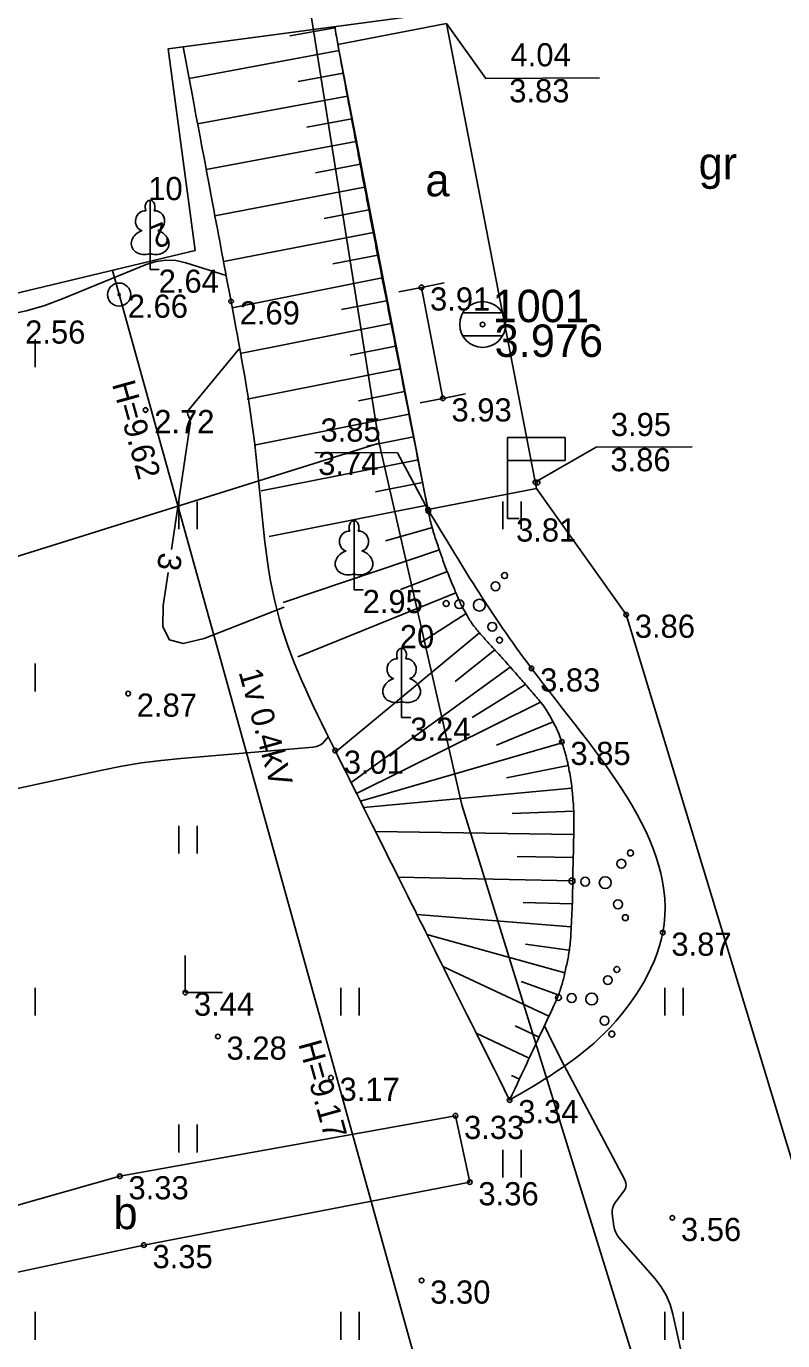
# Model space of a CAD drawing. Extents: x 321079 to 321220, y 257030 to 257220.
# Drawn here: x 321153.21 to 321169.55, y 257130.98 to 257159.36 of the extents above; entities that cross this region are included whole.
import ezdxf

# ---------------------------------------------------------------- set-up
doc = ezdxf.new("R2010")
doc.units = 0
for name, color, linetype in [('BUVE_SOLS_####_####_#', 7, 'Continuous'), ('CELI_CAPM_####_####_#', 7, 'Continuous'), ('CELI_CMAL_####_####_#', 7, 'Continuous'), ('CELI_CSEG_####_TKST_#', 7, 'Continuous'), ('CELI_ELEM_####_####_#', 7, 'Continuous'), ('ELEK_ELEM_####_####_#', 7, 'Continuous'), ('ELEK_VADV_ZSPR_####_#', 7, 'Continuous'), ('ELEK_VADV_ZSPR_TKST_#', 7, 'Continuous'), ('GEOD_ELEM_####_####_#', 7, 'Continuous'), ('GEOD_ELEM_####_TKST_#', 7, 'Continuous'), ('RAMI_UZMR_####_####_#', 7, 'Continuous'), ('RELJ_AATZ_####_TKST_#', 7, 'Continuous'), ('RELJ_ELEM_####_####_#', 7, 'Continuous'), ('RELJ_HORZ_####_TKST_#', 7, 'Continuous'), ('RELJ_HORZ_PAMT_####_#', 7, 'Continuous'), ('RELJ_HORZ_PUSH_####_#', 7, 'Continuous'), ('RELJ_NOGA_####_####_#', 7, 'Continuous'), ('RELJ_NOGL_####_####_#', 7, 'Continuous'), ('ROBZ_UZMR_####_####_#', 7, 'Continuous'), ('TERT_DIAM_####_TKST_#', 7, 'Continuous'), ('TERT_ELEM_####_####_#', 7, 'Continuous'), ('TERT_KONT_####_####_#', 7, 'Continuous')]:
    doc.layers.add(name, color=color, linetype=linetype)

msp = doc.modelspace()

# ---------------------------------------------------------------- linework, layer by layer
at = {"layer": 'BUVE_SOLS_####_####_#'}
for p, q in [((321162.233, 257153.819), (321161.742, 257153.724)), ((321161.251, 257153.629), (321161.742, 257153.724)), ((321162.206, 257151.328), (321161.742, 257153.724)), ((321161.715, 257151.233), (321162.206, 257151.328)), ((321162.697, 257151.423), (321162.206, 257151.328))]:
    msp.add_line(p, q, dxfattribs=at)
at = {"layer": 'CELI_CAPM_####_####_#'}
msp.add_lwpolyline([(321162.284, 257159.421), (321164.229, 257149.382), (321161.884, 257148.928), (321159.939, 257158.967)], close=True, dxfattribs=at)
at = {"layer": 'CELI_CMAL_####_####_#'}
for points in [[(321164.229, 257149.382), (321166.166, 257146.657), (321169.755, 257134.824), (321173.111, 257121.931), (321175.798, 257109.619)], [(321149.02, 257131.603), (321155.747, 257133.045), (321162.788, 257134.403), (321162.477, 257135.836), (321155.228, 257134.532), (321148.802, 257132.714)]]:
    msp.add_lwpolyline(points, dxfattribs=at)
at = {"layer": 'CELI_ELEM_####_####_#'}
for p, q in [((321163.601, 257148.735), (321163.601, 257150.485)), ((321163.601, 257150.485), (321164.851, 257150.485)), ((321164.851, 257150.485), (321164.851, 257149.985)), ((321163.601, 257149.985), (321164.851, 257149.985)), ((321163.601, 257148.735), (321163.851, 257148.735))]:
    msp.add_line(p, q, dxfattribs=at)
at = {"layer": 'ELEK_ELEM_####_####_#'}
for radius in [0.25, 0.0225]:
    msp.add_circle((321155.212, 257153.568), radius, dxfattribs=at)
at = {"layer": 'ELEK_VADV_ZSPR_####_#'}
msp.add_line((321165.672, 257115.939), (321155.067, 257154.09), dxfattribs=at)
at = {"layer": 'GEOD_ELEM_####_####_#'}
for p, q in [((321162.635, 257153.171), (321163.493, 257153.171)), ((321162.635, 257152.676), (321163.493, 257152.676))]:
    msp.add_line(p, q, dxfattribs=at)
for radius in [0.495, 0.05]:
    msp.add_circle((321163.064, 257152.923), radius, dxfattribs=at)
at = {"layer": 'RAMI_UZMR_####_####_#'}
msp.add_lwpolyline([(321107.5, 257141.5), (321108.611, 257133.395), (321131.584, 257099.382), (321150.327, 257105.322), (321177.121, 257109.842), (321183.308, 257111.386), (321177.517, 257137.442), (321172.561, 257161.05), (321156.27, 257158.872), (321156.852, 257154.517), (321139.352, 257150.329), (321114.57, 257145.337)], close=True, dxfattribs=at)
at = {"layer": 'RELJ_AATZ_####_TKST_#'}
for points in [[(321162.284, 257159.421), (321163.132, 257158.232), (321165.587, 257158.246)], [(321161.884, 257148.928), (321161.225, 257150.15), (321159.442, 257150.158)], [(321164.203, 257149.517), (321165.514, 257150.274), (321167.589, 257150.282)]]:
    msp.add_lwpolyline(points, dxfattribs=at)
at = {"layer": 'RELJ_ELEM_####_####_#'}
for centre in [(321161.742, 257153.724), (321157.629, 257153.423), (321162.206, 257151.328), (321155.782, 257151.076), (321155.785, 257151.077), (321164.203, 257149.517), (321164.251, 257149.509), (321161.884, 257148.928), (321161.893, 257148.894), (321166.166, 257146.657), (321164.12, 257145.497), (321155.407, 257144.954), (321164.775, 257143.911), (321159.879, 257143.721), (321166.956, 257139.792), (321156.642, 257138.496), (321157.346, 257137.548), (321159.787, 257136.658), (321163.648, 257136.176), (321162.477, 257135.836), (321155.228, 257134.532), (321162.788, 257134.403), (321167.163, 257133.632), (321155.747, 257133.045), (321161.746, 257132.28)]:
    msp.add_circle(centre, 0.05, dxfattribs=at)
at = {"layer": 'RELJ_HORZ_PAMT_####_#'}
for points in [[(321156.342, 257148.061), (321156.749, 257150.775), (321156.751, 257150.801), (321156.75, 257150.828), (321156.745, 257150.854), (321156.737, 257150.879), (321156.695, 257150.981), (321156.689, 257151.006), (321156.689, 257151.029), (321156.696, 257151.052), (321156.71, 257151.074), (321157.808, 257152.399)], [(321158.776, 257146.816), (321157.051, 257146.145), (321156.598, 257146.035), (321156.299, 257146.117), (321156.154, 257146.391), (321156.161, 257146.857), (321156.268, 257147.567)], [(321150.909, 257141.534), (321151.016, 257141.573), (321151.199, 257141.679), (321151.365, 257141.818), (321152.001, 257142.441), (321152.167, 257142.583), (321152.348, 257142.698), (321152.543, 257142.786), (321152.753, 257142.847), (321154.846, 257143.299), (321155.268, 257143.383), (321155.693, 257143.454), (321156.119, 257143.511), (321156.548, 257143.554), (321159.404, 257143.796), (321159.478, 257143.809), (321159.545, 257143.836), (321159.604, 257143.877), (321159.656, 257143.932), (321159.732, 257144.027)]]:
    msp.add_lwpolyline(points, dxfattribs=at)
at = {"layer": 'RELJ_HORZ_PUSH_####_#'}
for points in [[(321149.681, 257152.801), (321152.406, 257153.078), (321152.806, 257153.133), (321153.2, 257153.217), (321153.586, 257153.328), (321153.965, 257153.468), (321155.798, 257154.217), (321156.01, 257154.284), (321156.223, 257154.313), (321156.438, 257154.303), (321156.654, 257154.254), (321157.523, 257153.982), (321157.524, 257153.982)], [(321164.4, 257137.779), (321164.485, 257137.601), (321164.567, 257137.435), (321164.65, 257137.269), (321164.734, 257137.104), (321164.82, 257136.94), (321166.136, 257134.454), (321166.161, 257134.391), (321166.165, 257134.329), (321166.15, 257134.269), (321166.116, 257134.21), (321165.934, 257133.972), (321165.898, 257133.916), (321165.875, 257133.856), (321165.864, 257133.794), (321165.866, 257133.727), (321165.897, 257133.456), (321165.91, 257133.39), (321165.932, 257133.328), (321165.963, 257133.271), (321166.003, 257133.217), (321166.789, 257132.319), (321166.923, 257132.146), (321167.032, 257131.961), (321167.116, 257131.763), (321167.176, 257131.552), (321167.47, 257130.219)]]:
    msp.add_lwpolyline(points, dxfattribs=at)
at = {"layer": 'RELJ_NOGA_####_####_#'}
for p, q in [((321159.873, 257159.331), (321158.899, 257159.154)), ((321159.963, 257158.839), (321156.723, 257158.237)), ((321160.054, 257158.348), (321159.082, 257158.167)), ((321160.145, 257157.856), (321156.908, 257157.254)), ((321160.237, 257157.365), (321159.266, 257157.184)), ((321160.328, 257156.873), (321157.093, 257156.271)), ((321160.42, 257156.382), (321159.451, 257156.195)), ((321160.515, 257155.891), (321157.282, 257155.267)), ((321160.609, 257155.4), (321159.639, 257155.213)), ((321160.704, 257154.909), (321157.467, 257154.285)), ((321160.799, 257154.418), (321159.827, 257154.23)), ((321160.893, 257153.927), (321157.653, 257153.285)), ((321160.991, 257153.436), (321160.015, 257153.243)), ((321161.088, 257152.946), (321157.823, 257152.299)), ((321161.185, 257152.455), (321160.2, 257152.26)), ((321161.282, 257151.965), (321157.977, 257151.31)), ((321161.379, 257151.474), (321160.381, 257151.277)), ((321161.477, 257150.984), (321158.126, 257150.32)), ((321161.574, 257150.494), (321160.562, 257150.293)), ((321161.671, 257150.003), (321158.282, 257149.332)), ((321161.768, 257149.513), (321160.747, 257149.31)), ((321161.865, 257149.022), (321158.451, 257148.346)), ((321161.979, 257148.536), (321160.966, 257148.254)), ((321162.132, 257148.059), (321158.755, 257146.919)), ((321162.303, 257147.59), (321161.287, 257147.199)), ((321162.489, 257147.126), (321159.075, 257145.747)), ((321162.712, 257146.679), (321161.741, 257146.065)), ((321162.996, 257146.268), (321159.891, 257143.697)), ((321163.324, 257145.891), (321162.469, 257145.211)), ((321163.662, 257145.523), (321160.224, 257143.031)), ((321164, 257145.154), (321162.835, 257144.436)), ((321164.313, 257144.764), (321160.342, 257142.794)), ((321164.585, 257144.345), (321163.361, 257143.837)), ((321164.782, 257143.887), (321160.425, 257142.629)), ((321164.909, 257143.403), (321163.583, 257143.133)), ((321164.992, 257142.911), (321160.491, 257142.496)), ((321165.027, 257142.412), (321163.703, 257142.362)), ((321165.031, 257141.912), (321160.75, 257141.978)), ((321165.023, 257141.412), (321163.813, 257141.437)), ((321165.012, 257140.912), (321161.243, 257140.991)), ((321164.998, 257140.413), (321163.943, 257140.444)), ((321164.976, 257139.913), (321161.645, 257140.185)), ((321164.84, 257138.924), (321161.861, 257139.754)), ((321164.928, 257139.416), (321163.994, 257139.544)), ((321164.497, 257137.987), (321162.207, 257139.06)), ((321164.697, 257138.445), (321163.898, 257138.733)), ((321164.072, 257137.081), (321162.928, 257137.618)), ((321164.285, 257137.534), (321163.77, 257137.776)), ((321163.86, 257136.629), (321163.689, 257136.709)), ((321163.648, 257136.176), (321163.639, 257136.18))]:
    msp.add_line(p, q, dxfattribs=at)
msp.add_open_spline([(321163.648, 257136.176), (321163.961, 257136.845), (321164.275, 257137.513), (321164.588, 257138.182), (321164.709, 257138.44), (321164.794, 257138.714), (321164.857, 257138.994), (321164.92, 257139.279), (321164.96, 257139.565), (321164.975, 257139.854), (321164.989, 257140.146), (321165.004, 257140.439), (321165.009, 257140.732), (321165.012, 257140.878), (321165.012, 257141.024), (321165.016, 257141.169), (321165.019, 257141.313), (321165.023, 257141.457), (321165.027, 257141.601), (321165.031, 257141.794), (321165.034, 257141.986), (321165.035, 257142.178), (321165.037, 257142.371), (321165.025, 257142.564), (321165.008, 257142.756), (321164.991, 257142.951), (321164.964, 257143.143), (321164.927, 257143.334), (321164.908, 257143.432), (321164.886, 257143.527), (321164.861, 257143.623), (321164.836, 257143.72), (321164.807, 257143.816), (321164.775, 257143.911), (321164.722, 257144.068), (321164.653, 257144.218), (321164.574, 257144.366), (321164.497, 257144.511), (321164.414, 257144.651), (321164.309, 257144.777), (321164.097, 257145.029), (321163.882, 257145.275), (321163.665, 257145.521), (321163.45, 257145.765), (321163.226, 257146.002), (321163.012, 257146.248), (321162.854, 257146.43), (321162.725, 257146.634), (321162.614, 257146.848), (321162.577, 257146.92), (321162.544, 257146.992), (321162.513, 257147.067), (321162.386, 257147.37), (321162.262, 257147.673), (321162.154, 257147.984), (321162.047, 257148.294), (321161.948, 257148.607), (321161.884, 257148.928), (321161.716, 257149.764), (321161.55, 257150.6), (321161.385, 257151.436), (321161.22, 257152.272), (321161.054, 257153.108), (321160.89, 257153.944), (321160.726, 257154.78), (321160.565, 257155.617), (321160.406, 257156.454), (321160.248, 257157.291), (321160.091, 257158.128), (321159.939, 257158.967), (321159.915, 257159.095), (321159.892, 257159.224), (321159.869, 257159.353)], degree=3, dxfattribs=at)
at = {"layer": 'RELJ_NOGL_####_####_#'}
msp.add_open_spline([(321163.648, 257136.176), (321162.392, 257138.691), (321161.135, 257141.206), (321159.879, 257143.721), (321158.395, 257146.691), (321158.243, 257150.16), (321157.629, 257153.423), (321157.284, 257155.254), (321156.94, 257157.085), (321156.595, 257158.915)], degree=3, dxfattribs=at)
at = {"layer": 'ROBZ_UZMR_####_####_#'}
for p, q in [((321160.832, 257150.36), (321153.272, 257197.779)), ((321109.842, 257134.432), (321160.832, 257150.36)), ((321162.618, 257142.549), (321160.832, 257150.36)), ((321171.804, 257112.938), (321162.618, 257142.549))]:
    msp.add_line(p, q, dxfattribs=at)
at = {"layer": 'TERT_ELEM_####_####_#'}
for p, q in [((321155.88, 257154.455), (321155.88, 257154.108)), ((321155.88, 257154.108), (321156.08, 257154.108)), ((321153.4, 257152), (321153.4, 257152.6)), ((321156.5, 257148.5), (321156.5, 257149.1)), ((321156.9, 257148.5), (321156.9, 257149.1)), ((321163.5, 257148.5), (321163.5, 257149.1)), ((321163.9, 257148.5), (321163.9, 257149.1)), ((321160.286, 257147.538), (321160.286, 257147.191)), ((321160.286, 257147.191), (321160.486, 257147.191)), ((321153.4, 257145), (321153.4, 257145.6)), ((321161.315, 257144.78), (321161.315, 257144.433)), ((321161.315, 257144.433), (321161.515, 257144.433)), ((321156.5, 257141.5), (321156.5, 257142.1)), ((321156.9, 257141.5), (321156.9, 257142.1)), ((321156.642, 257139.296), (321156.642, 257138.496)), ((321153.4, 257138), (321153.4, 257138.6)), ((321156.642, 257138.496), (321157.442, 257138.496)), ((321160, 257138), (321160, 257138.6)), ((321160.4, 257138), (321160.4, 257138.6)), ((321167, 257138), (321167, 257138.6)), ((321167.4, 257138), (321167.4, 257138.6)), ((321156.5, 257135.045), (321156.5, 257135.645)), ((321156.9, 257135.045), (321156.9, 257135.645)), ((321163.5, 257134.5), (321163.5, 257135.1)), ((321163.9, 257134.5), (321163.9, 257135.1)), ((321153.4, 257131), (321153.4, 257131.6)), ((321160, 257131), (321160, 257131.6)), ((321160.4, 257131), (321160.4, 257131.6)), ((321167, 257131), (321167, 257131.6)), ((321167.4, 257131), (321167.4, 257131.6))]:
    msp.add_line(p, q, dxfattribs=at)
for points in [[(321155.88, 257155.608), (321155.88, 257154.455)], [(321155.97, 257155.376), (321155.969, 257155.377)], [(321160.286, 257148.691), (321160.286, 257147.538)], [(321160.376, 257148.459), (321160.375, 257148.46)], [(321161.315, 257145.933), (321161.315, 257144.78)], [(321161.405, 257145.701), (321161.404, 257145.702)]]:
    msp.add_lwpolyline(points, dxfattribs=at)
for centre, radius in [((321163.539, 257147.501), 0.064), ((321163.343, 257147.27), 0.096), ((321162.561, 257146.883), 0.096), ((321162.995, 257146.862), 0.128), ((321162.277, 257146.896), 0.064), ((321163.272, 257146.395), 0.096), ((321163.429, 257146.106), 0.064), ((321166.257, 257141.51), 0.064), ((321166.061, 257141.278), 0.096), ((321164.995, 257140.905), 0.064), ((321165.28, 257140.891), 0.096), ((321165.713, 257140.87), 0.128), ((321165.99, 257140.404), 0.096), ((321166.147, 257140.114), 0.064), ((321165.965, 257138.996), 0.064), ((321165.769, 257138.765), 0.096), ((321164.703, 257138.391), 0.064), ((321164.987, 257138.378), 0.096), ((321165.421, 257138.357), 0.128), ((321165.698, 257137.89), 0.096), ((321165.855, 257137.601), 0.064)]:
    msp.add_circle(centre, radius, dxfattribs=at)
for centre, major_axis, ratio, start_param, end_param in [((321155.88, 257155.458), (0, -0.15), 0.707107, 3.14537, 5.287485), ((321155.88, 257155.458), (0, -0.15), 0.707107, 0.995701, 3.137816), ((321155.752, 257155.163), (-0.039, -0.212), 0.861323, 3.141593, 6.283185), ((321156.008, 257155.163), (0.039, -0.212), 0.861323, 0, 3.141593), ((321155.79, 257154.701), (0.307, 0.095), 0.814445, 1.570796, 4.752015), ((321155.97, 257154.701), (-0.307, 0.095), 0.814445, 1.531171, 4.712389), ((321160.286, 257148.541), (0, -0.15), 0.707107, 3.14537, 5.287485), ((321160.286, 257148.541), (0, -0.15), 0.707107, 0.995701, 3.137816), ((321160.158, 257148.246), (-0.039, -0.212), 0.861323, 3.141593, 6.283185), ((321160.414, 257148.246), (0.039, -0.212), 0.861323, 0, 3.141593), ((321160.196, 257147.784), (0.307, 0.095), 0.814445, 1.570796, 4.752015), ((321160.376, 257147.784), (-0.307, 0.095), 0.814445, 1.531171, 4.712389), ((321161.315, 257145.783), (0, -0.15), 0.707107, 3.14537, 5.287485), ((321161.315, 257145.783), (0, -0.15), 0.707107, 0.995701, 3.137816), ((321161.187, 257145.488), (-0.039, -0.212), 0.861323, 3.141593, 6.283185), ((321161.443, 257145.488), (0.039, -0.212), 0.861323, 0, 3.141593), ((321161.225, 257145.026), (0.307, 0.095), 0.814445, 1.570796, 4.752015), ((321161.405, 257145.026), (-0.307, 0.095), 0.814445, 1.531171, 4.712389)]:
    msp.add_ellipse(centre, major_axis=major_axis, ratio=ratio, start_param=start_param, end_param=end_param, dxfattribs=at)
at = {"layer": 'TERT_KONT_####_####_#'}
msp.add_spline([(321163.648, 257136.176), (321165.582, 257137.509), (321166.956, 257139.792), (321164.12, 257145.497), (321161.884, 257148.928)], degree=3, dxfattribs=at)

# ---------------------------------------------------------------- texts
at = {"layer": 'CELI_CSEG_####_TKST_#'}
for s, p in [('gr', (321167.731, 257156.055)), ('a', (321161.829, 257155.69)), ('b', (321155.09, 257133.389))]:
    msp.add_text(s, height=0.7, dxfattribs=at).set_placement(p)
at = {"layer": 'ELEK_VADV_ZSPR_TKST_#'}
for s, p in [('H=9.62', (321155.054, 257151.637)), ('1v 0.4kV', (321157.789, 257145.419)), ('H=9.17', (321159.08, 257137.391))]:
    msp.add_text(s, height=0.5, rotation=285.5347, dxfattribs=at).set_placement(p)
at = {"layer": 'GEOD_ELEM_####_TKST_#'}
for s, p in [(' 1001', (321163.019, 257152.973)), (' 3.976', (321163.064, 257152.223))]:
    msp.add_text(s, height=0.7, dxfattribs=at).set_placement(p)
at = {"layer": 'RELJ_AATZ_####_TKST_#'}
for s, p in [(' 4.04', (321163.481, 257158.497)), (' 3.83', (321163.453, 257157.72)), (' 2.64', (321155.88, 257153.608)), (' 2.66', (321155.212, 257153.068)), (' 3.91', (321161.742, 257153.224)), (' 2.69', (321157.629, 257152.923)), (' 2.56', (321152.996, 257152.51)), (' 3.93', (321162.206, 257150.828)), (' 2.72', (321155.782, 257150.576)), (' 2.72', (321155.785, 257150.577)), (' 3.95', (321165.648, 257150.515)), (' 3.85', (321159.376, 257150.394)), (' 3.74', (321159.326, 257149.673)), (' 3.86', (321165.638, 257149.754)), (' 3.81', (321163.601, 257148.235)), (' 2.95', (321160.286, 257146.691)), (' 3.86', (321166.166, 257146.157)), (' 3.83', (321164.12, 257144.997)), (' 2.87', (321155.407, 257144.454)), (' 3.24', (321161.315, 257143.933)), (' 3.85', (321164.775, 257143.411)), (' 3.01', (321159.879, 257143.221)), (' 3.87', (321166.956, 257139.292)), (' 3.44', (321156.642, 257137.996)), (' 3.28', (321157.346, 257137.048)), (' 3.17', (321159.787, 257136.158)), (' 3.34', (321163.648, 257135.676)), (' 3.33', (321162.477, 257135.336)), (' 3.33', (321155.228, 257134.032)), (' 3.36', (321162.788, 257133.903)), (' 3.56', (321167.163, 257133.132)), (' 3.35', (321155.747, 257132.545)), (' 3.30', (321161.746, 257131.78))]:
    msp.add_text(s, height=0.5, dxfattribs=at).set_placement(p)
at = {"layer": 'RELJ_HORZ_####_TKST_#'}
for s, rotation, p in [('2', 202.2457, (321156.173, 257155.151)), ('3', 261.4664, (321156.082, 257148.017))]:
    msp.add_text(s, height=0.5, rotation=rotation, dxfattribs=at).set_placement(p)
at = {"layer": 'TERT_DIAM_####_TKST_#'}
for s, p in [(' 10', (321155.655, 257155.608)), (' 20', (321161.09, 257145.933))]:
    msp.add_text(s, height=0.5, dxfattribs=at).set_placement(p)

doc.saveas('drawing.dxf')
